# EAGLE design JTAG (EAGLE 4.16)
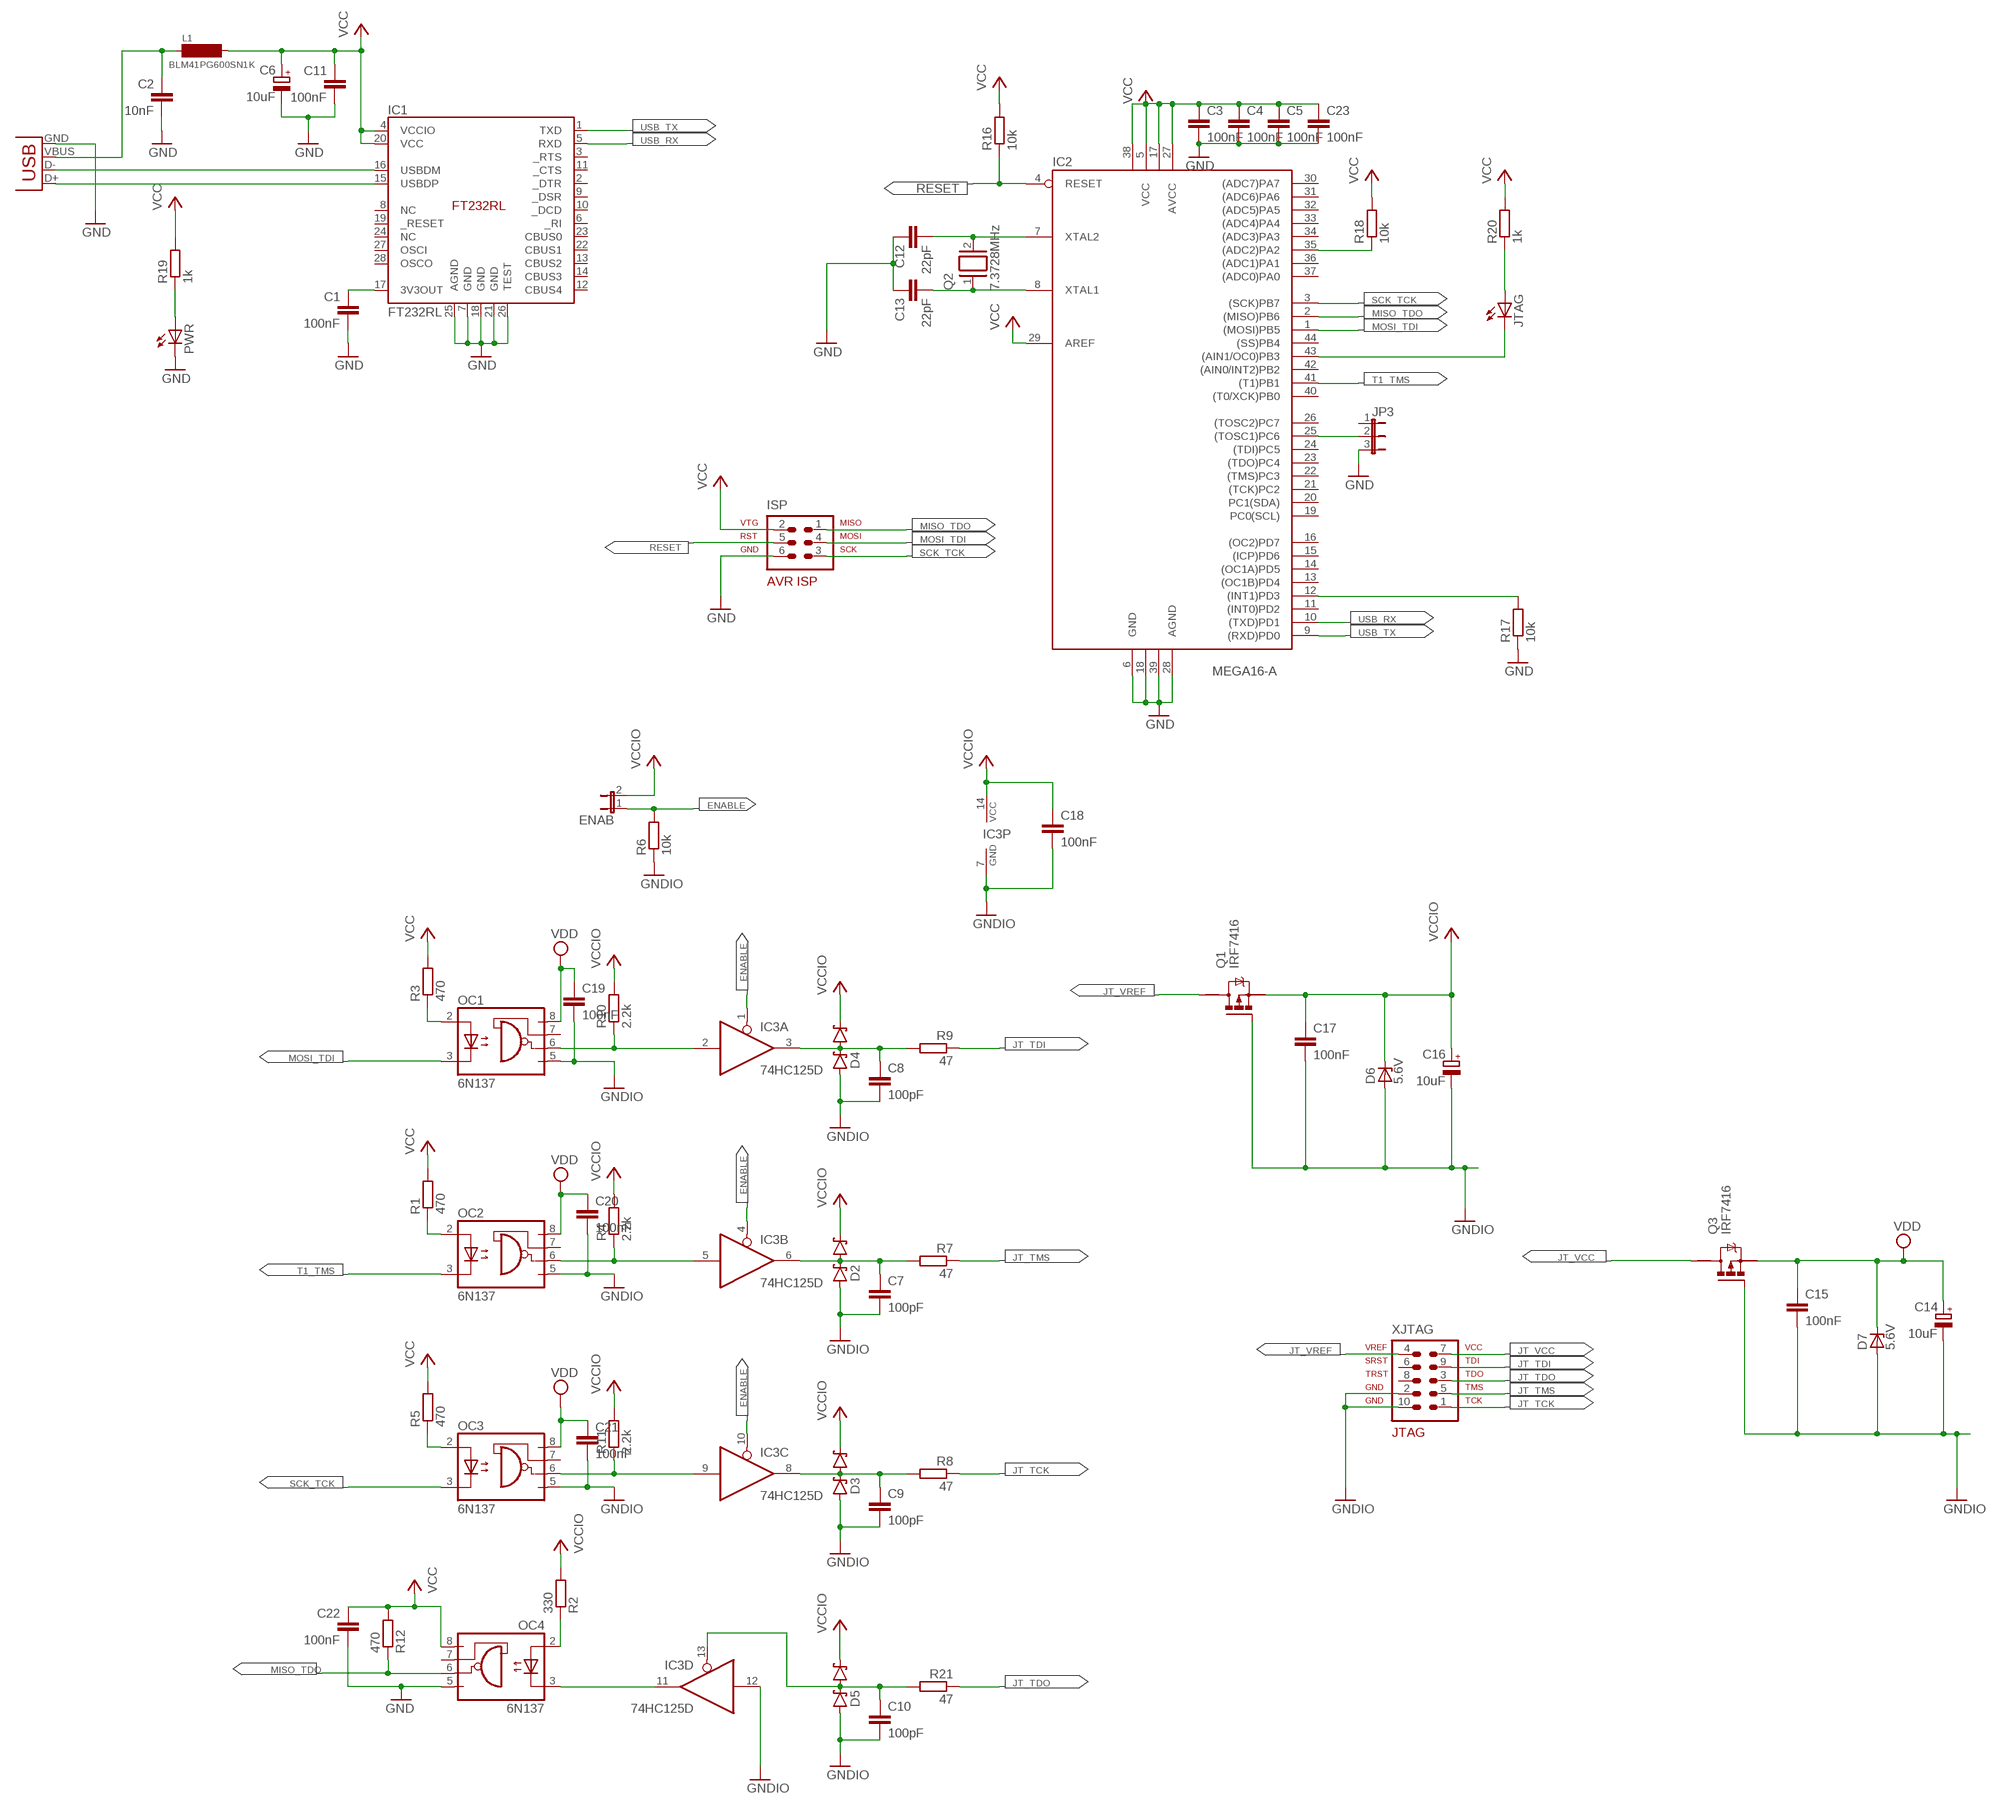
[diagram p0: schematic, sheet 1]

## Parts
C1  100nF  C-EUC0805  [C0805]
C2  10nF  C-EUC0805  [C0805]
C3  100nF  C-EUC0805  [C0805]
C4  100nF  C-EUC0805  [C0805]
C5  100nF  C-EUC0805  [C0805]
C6  10uF  CPOL-EUB  [PANASONIC_B]
C7  100pF  C-EUC0805  [C0805]
C8  100pF  C-EUC0805  [C0805]
C9  100pF  C-EUC0805  [C0805]
C10  100pF  C-EUC0805  [C0805]
C11  100nF  C-EUC0805  [C0805]
C12  22pF  C-EUC0805  [C0805]
C13  22pF  C-EUC0805  [C0805]
C14  10uF  CPOL-EUB  [PANASONIC_B]
C15  100nF  C-EUC0805  [C0805]
C16  10uF  CPOL-EUB  [PANASONIC_B]
C17  100nF  C-EUC0805  [C0805]
C18  100nF  C-EUC0805  [C0805]
C19  100nF  C-EUC0805  [C0805]
C20  100nF  C-EUC0805  [C0805]
C21  100nF  C-EUC0805  [C0805]
C22  100nF  C-EUC0805  [C0805]
C23  100nF  C-EUC0805  [C0805]
D2  DUAL_SCHOTTKY_CACASOT23  [SOT23]
D3  DUAL_SCHOTTKY_CACASOT23  [SOT23]
D4  DUAL_SCHOTTKY_CACASOT23  [SOT23]
D5  DUAL_SCHOTTKY_CACASOT23  [SOT23]
D6  5.6V  ZENER-DIODESOT23  [SOT23]
D7  5.6V  ZENER-DIODESOT23  [SOT23]
ENAB  JP1E  [JP1]
IC1  FT232RL  [SSOP-28]
IC2  MEGA16-A  [TQFP44]
IC3  74HC125D  [SO14]
ISP  AVR-ISP-6  [AVR-ISP-6]
JP3  JP2E  [JP2]
JTAG  LED5MM  [LED5MM]
L1  BLM41PG600SN1K  [1806]
OC1  6N137  [DIL08]
OC2  6N137  [DIL08]
OC3  6N137  [DIL08]
OC4  6N137  [DIL08]
PWR  LED5MM  [LED5MM]
Q1  IRF7416  P-MOSFET-SO8  [SO-08]
Q2  7.3728MHz  XTAL/S  [QS]
Q3  IRF7416  P-MOSFET-SO8  [SO-08]
R1  470  R-EU_R0805  [R0805]
R2  330  R-EU_R0805  [R0805]
R3  470  R-EU_R0805  [R0805]
R4  2.2k  R-EU_R0805  [R0805]
R5  470  R-EU_R0805  [R0805]
R6  10k  R-EU_R0805  [R0805]
R7  47  R-EU_R0805  [R0805]
R8  47  R-EU_R0805  [R0805]
R9  47  R-EU_R0805  [R0805]
R10  2.2k  R-EU_R0805  [R0805]
R11  2.2k  R-EU_R0805  [R0805]
R12  470  R-EU_R0805  [R0805]
R16  10k  R-EU_R0805  [R0805]
R17  10k  R-EU_R0805  [R0805]
R18  10k  R-EU_R0805  [R0805]
R19  1k  R-EU_R0805  [R0805]
R20  1k  R-EU_R0805  [R0805]
R21  47  R-EU_R0805  [R0805]
USB  USB-B-H  [USB-B-H]
XJTAG  AVR-JTAG-10-R  [AVR-JTAG-10R]

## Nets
D+: IC1.15(USBDP) USB.D+
D-: IC1.16(USBDM) USB.D-
ENABLE: ENAB.1 IC3.1(A:OE) IC3.4(B:OE) IC3.10(C:OE) R6.2
GND: C1.2 C2.2 C3.2 C4.2 C5.2 C6.- C11.2 C12.1 C13.1 C22.2 C23.2 IC1.7(GND) IC1.18(GND) IC1.21(GND) IC1.25(AGND) IC1.26(TEST) IC2.6(GND) IC2.18(GND1) IC2.28(AGND) IC2.39(GND2) ISP.6 JP3.3 OC4.5(GND) PWR.K(C) R17.1 USB.GND
GNDIO: C7.2 C8.2 C9.2 C10.2 C14.- C15.2 C16.- C17.2 C18.2 C19.2 C20.2 C21.2 D2.1(A) D3.1(A) D4.1(A) D5.1(A) D6.1(A) D7.1(A) IC3.7(P:GND) IC3.12(D:I) OC1.5(GND) OC2.5(GND) OC3.5(GND) Q1.4(G) Q3.4(G) R6.1 XJTAG.2 XJTAG.10
JT_TCK: R8.1 XJTAG.1
JT_TDI: R9.1 XJTAG.9
JT_TDO: R21.1 XJTAG.3
JT_TMS: R7.1 XJTAG.5
JT_VCC: Q3.5(D) XJTAG.7
JT_VREF: Q1.5(D) XJTAG.4
MISO_TDO: IC2.2((MISO)PB6) ISP.1 OC4.6(VO) R12.1
MOSI_TDI: IC2.1((MOSI)PB5) ISP.4 OC1.3(C)
N$1: IC2.12((INT1)PD3) R17.2
N$4: C13.2 IC2.8(XTAL1) Q2.1
N$5: C12.2 IC2.7(XTAL2) Q2.2
N$6: IC2.25((TOSC1)PC6) JP3.2
N$8: C8.1 D4.3(AC) IC3.3(A:O) R9.2
N$9: IC2.35((ADC2)PA2) R18.1
N$10: PWR.A R19.1
N$11: OC4.2(A) R2.1
N$12: C7.1 D2.3(AC) IC3.6(B:O) R7.2
N$13: JTAG.A R20.1
N$14: OC1.2(A) R3.1
N$15: OC2.2(A) R1.1
N$17: IC3.5(B:I) OC2.6(VO) R4.1
N$18: C9.1 D3.3(AC) IC3.8(C:O) R8.2
N$20: C10.1 D5.3(AC) IC3.13(D:OE) R21.2
N$21: IC3.11(D:O) OC4.3(C)
N$22: IC2.43((AIN1/OC0)PB3) JTAG.K(C)
N$24: IC3.2(A:I) OC1.6(VO) R10.1
N$26: C2.1 L1.P$1 USB.VBUS
N$35: C1.1 IC1.17(3V3OUT)
N$36: OC3.2(A) R5.1
N$37: IC3.9(C:I) OC3.6(VO) R11.1
RESET: IC2.4(RESET) ISP.5 R16.1
SCK_TCK: IC2.3((SCK)PB7) ISP.3 OC3.3(C)
T1_TMS: IC2.41((T1)PB1) OC2.3(C)
USB_RX: IC1.5(RXD) IC2.10((TXD)PD1)
USB_TX: IC1.1(TXD) IC2.9((RXD)PD0)
VCC: C3.1 C4.1 C5.1 C6.+ C11.1 C22.1 C23.1 IC1.4(VCCIO) IC1.20(VCC) IC2.5(VCC) IC2.17(VCC1) IC2.27(AVCC) IC2.29(AREF) IC2.38(VCC2) ISP.2 L1.P$2 OC4.8(VCC) R1.2 R3.2 R5.2 R12.2 R16.2 R18.2 R19.2 R20.2
VCCIO: C16.+ C17.1 C18.1 D2.2(C) D3.2(C) D4.2(C) D5.2(C) D6.3(C) ENAB.2 IC3.14(P:VCC) Q1.1(S) R2.2 R4.2 R10.2 R11.2
VDD: C14.+ C15.1 C19.1 C20.1 C21.1 D7.3(C) OC1.8(VCC) OC2.8(VCC) OC3.8(VCC) Q3.1(S)
Unconnected: IC1.2(_DTR) IC1.3(_RTS) IC1.6(_RI) IC1.8(NC) IC1.9(_DSR) IC1.10(_DCD) IC1.11(_CTS) IC1.12(CBUS4) IC1.13(CBUS2) IC1.14(CBUS3) IC1.19(_RESET) IC1.22(CBUS1) IC1.23(CBUS0) IC1.24(NC) IC1.27(OSCI) IC1.28(OSCO) IC2.11((INT0)PD2) IC2.13((OC1B)PD4) IC2.14((OC1A)PD5) IC2.15((ICP)PD6) IC2.16((OC2)PD7) IC2.19(PC0(SCL)) IC2.20(PC1(SDA)) IC2.21((TCK)PC2) IC2.22((TMS)PC3) IC2.23((TDO)PC4) IC2.24((TDI)PC5) IC2.26((TOSC2)PC7) IC2.30((ADC7)PA7) IC2.31((ADC6)PA6) IC2.32((ADC5)PA5) IC2.33((ADC4)PA4) IC2.34((ADC3)PA3) IC2.36((ADC1)PA1) IC2.37((ADC0)PA0) IC2.40((T0/XCK)PB0) IC2.42((AIN0/INT2)PB2) IC2.44((SS)PB4) JP3.1 OC1.7(VE) OC2.7(VE) OC3.7(VE) OC4.7(VE) Q1.2(S) Q1.3(S) Q1.6(D) Q1.7(D) Q1.8(D) Q3.2(S) Q3.3(S) Q3.6(D) Q3.7(D) Q3.8(D) XJTAG.6 XJTAG.8

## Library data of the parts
C1-C5 C7-C13 C15 C17-C23 = thomas4:C-EU: CAPACITOR, European symbol
C6 C14 C16 = thomas4:CPOL-EU: POLARIZED CAPACITOR, European symbol
D2-D5 = Thomas2:DUAL_SCHOTTKY_CACA: 2 Diodes - Cathode-Anode|Cathode-Anode
D6 D7 = diode:ZENER-DIODE: Z-Diode
ENAB = thomas-jumper:JP1E: JUMPER
IC1 = thomas-ftdi:FT232RL
IC2 = atmel2:MEGA16: MICROCONTROLLER 16 Kbytes FLASH 1 kbytes SRAM 512 bytes EEPROM USART 8-channel 10 bit ADC
IC3 = thomas-74:74*125: Quad bus BUFFER, 3-state
ISP = atmel2:AVR-ISP-6: AVR ISP-6 Serial Programming Header
JP3 = thomas-jumper:JP2E: JUMPER
JTAG PWR = led:LED: LED
L1 = Thomas:BLM41
OC1-OC4 = thomas5:6N137: MOTOROLA OPTO COUPLER
Q1 Q3 = transistor-power:P-MOSFET-SO8: P-Channel MOSFET Example: FDS4435A; P-Channel Logic Level PowerTrench® MOSFET FDS4465; P-Channel 1.8V Specified PowerTrench® MOSFET Source: www.fairchildsemi.com
Q2 = special:XTAL/S: CRYSTAL
R1-R12 R16-R21 = thomas4:R-EU_
USB = thomas-usb:USB: USB Connectors
XJTAG = atmel2:AVR-JTAG-10: AVR JTAG Debug/Programming Header

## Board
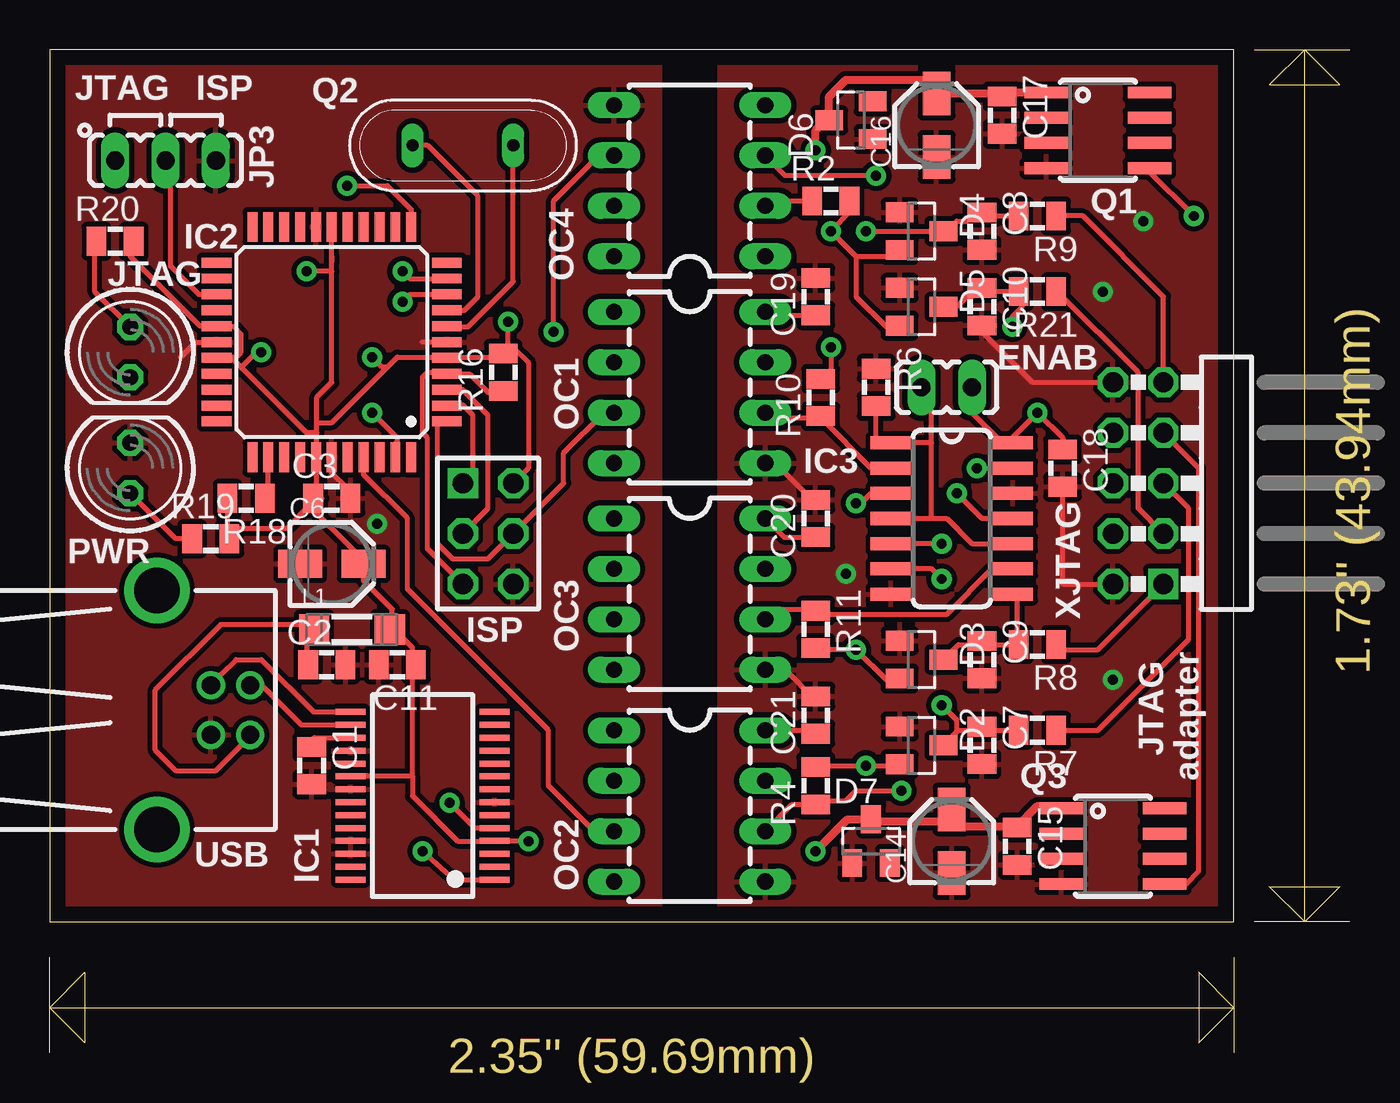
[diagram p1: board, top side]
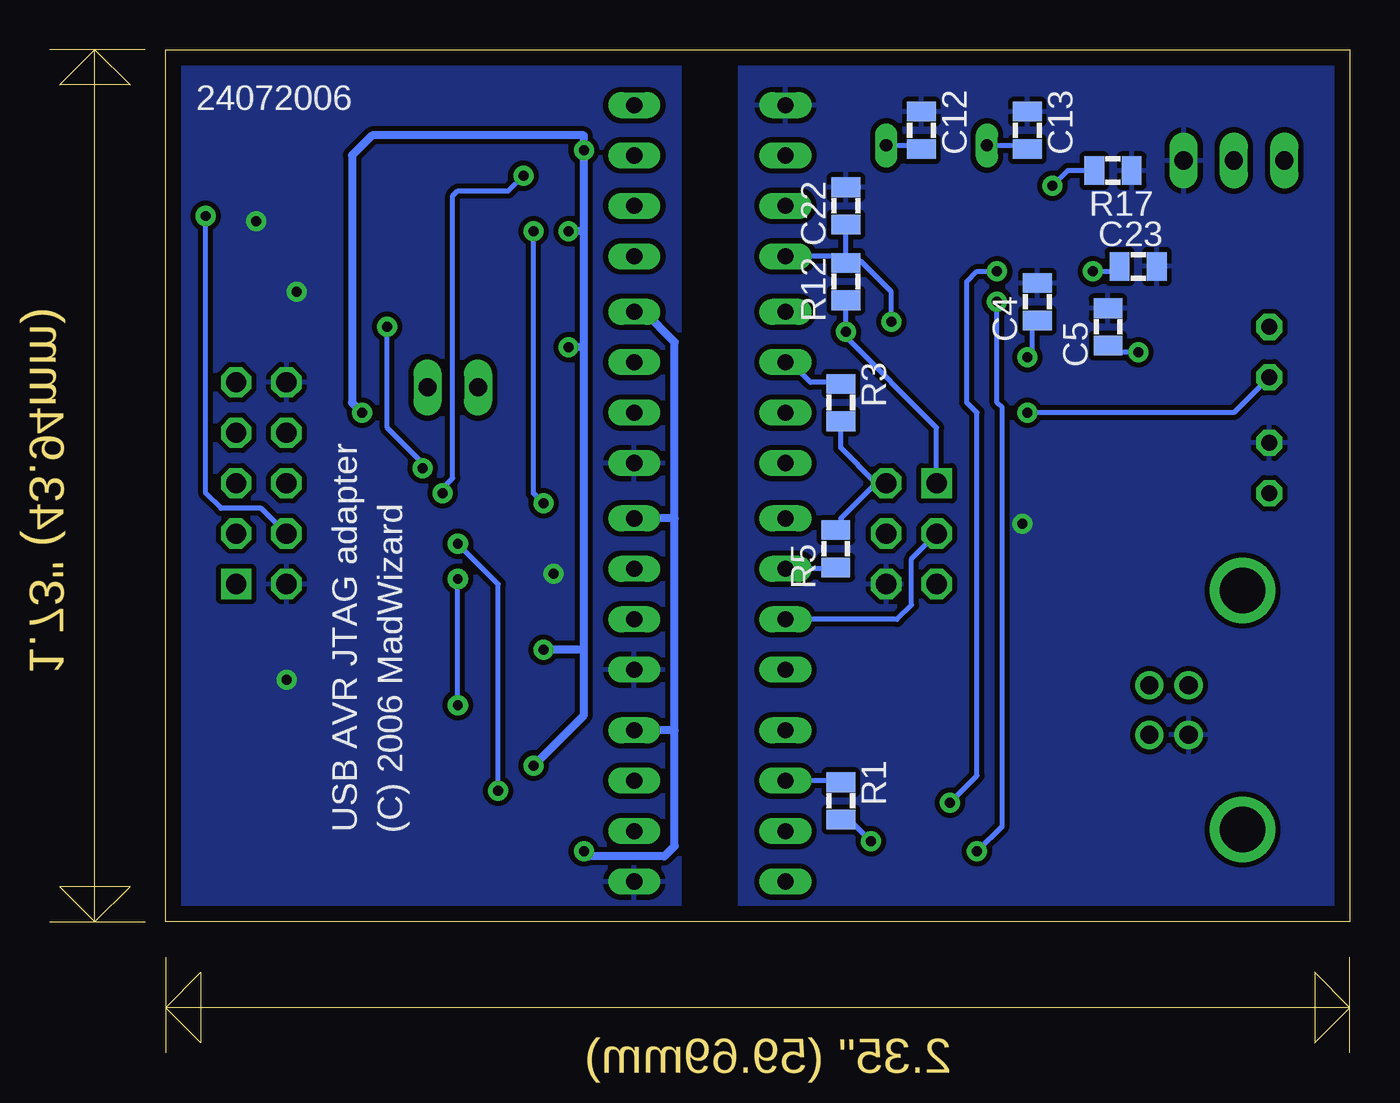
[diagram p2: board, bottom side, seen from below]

Size 65.53 x 50.55 mm. Coordinates in mm from the lower left corner, seen from the top.
Outline: 59.69,4.83 59.69,2.29
Outline: 59.69,2.29 59.69,0
Outline: 0,0 0,2.29
Outline: 0,2.29 0,4.83
Outline: 0,2.29 59.69,2.29
Outline: 59.69,2.29 57.91,4.06 57.91,0.51 59.69,2.29
Outline: 0,2.29 1.78,4.06 1.78,0.51 0,2.29
Outline: 60.71,50.55 63.25,50.55
Outline: 63.25,50.55 65.53,50.55
Outline: 65.53,6.6 63.25,6.6
Outline: 63.25,6.6 60.71,6.6
Outline: 63.25,6.6 63.25,50.55
Outline: 63.25,50.55 61.47,48.77 65.02,48.77 63.25,50.55
Outline: 63.25,6.6 61.47,8.38 65.02,8.38 63.25,6.6
Outline: 0,6.6 59.69,6.6 59.69,50.55 0,50.55 0,6.6
Copper layers (1*16): Top 0.0175mm / dielectric 1.55mm / Bottom 0.0175mm
Design rules "default": minimum track width 10mil, minimum drill 16mil, track to track 9mil, track to pad 9mil, pad to pad 9mil, via to via 9mil, smd to smd 9mil, copper to edge 30mil, drill to drill 10mil, minimum pad ring 10mil, minimum via ring 10mil, stop-mask expansion 4mil, vias tented up to drill 0mil, thermal gap 10mil

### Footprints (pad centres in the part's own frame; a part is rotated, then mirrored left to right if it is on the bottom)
C0805 = smd 0.991 x 1.448: 1 -0.94,0; 2 0.94,0
PANASONIC_B = smd 2.2 x 1.4: + 1.6,0; - -1.6,0
SOT23 = smd 1 x 1.4: 1 -0.95,-1.1; 2 0.95,-1.1; 3 0,1.1
JP1 = drill 0.914 long: 1 0,-1.27; 2 0,1.27
SSOP-28 = smd 0.3 x 1.5: 1 -4.225,-3.625; 2 -3.575,-3.625; 3 -2.925,-3.625; 4 -2.275,-3.625; 5 -1.625,-3.625; 6 -0.975,-3.625; 7 -0.325,-3.625; 8 0.325,-3.625; 9 0.975,-3.625; 10 1.625,-3.625; 11 2.275,-3.625; 12 2.925,-3.625; 13 3.575,-3.625; 14 4.225,-3.625; 15 4.225,3.625; 16 3.575,3.625; 17 2.925,3.625; 18 2.275,3.625; 19 1.625,3.625; 20 0.975,3.625; 21 0.325,3.625; 22 -0.325,3.625; 23 -0.975,3.625; 24 -1.625,3.625; 25 -2.275,3.625; 26 -2.925,3.625; 27 -3.575,3.625; 28 -4.225,3.625
TQFP44 = smd 1.5 x 0.5: 1 -5.8,4; 2 -5.8,3.2; 3 -5.8,2.4; 4 -5.8,1.6; 5 -5.8,0.8; 6 -5.8,0; 7 -5.8,-0.8; 8 -5.8,-1.6; 9 -5.8,-2.4; 10 -5.8,-3.2; 11 -5.8,-4; 23 5.8,-4; 24 5.8,-3.2; 25 5.8,-2.4; 26 5.8,-1.6; 27 5.8,-0.8; 28 5.8,0; 29 5.8,0.8; 30 5.8,1.6; 31 5.8,2.4; 32 5.8,3.2; 33 5.8,4 | smd 0.5 x 1.5: 12 -4,-5.8; 13 -3.2,-5.8; 14 -2.4,-5.8; 15 -1.6,-5.8; 16 -0.8,-5.8; 17 0,-5.8; 18 0.8,-5.8; 19 1.6,-5.8; 20 2.4,-5.8; 21 3.2,-5.8; 22 4,-5.8; 34 4,5.8; 35 3.2,5.8; 36 2.4,5.8; 37 1.6,5.8; 38 0.8,5.8; 39 0,5.8; 40 -0.8,5.8; 41 -1.6,5.8; 42 -2.4,5.8; 43 -3.2,5.8; 44 -4,5.8
SO14 = smd 0.66 x 2.032: 1 -3.81,-3.073; 2 -2.54,-3.073; 3 -1.27,-3.073; 4 0,-3.073; 5 1.27,-3.073; 6 2.54,-3.073; 7 3.81,-3.073; 8 3.81,3.073; 9 2.54,3.073; 10 1.27,3.073; 11 0,3.073; 12 -1.27,3.073; 13 -2.54,3.073; 14 -3.81,3.073
AVR-ISP-6 = drill 1.016 square: 1 -2.54,-1.27 | drill 1.016 octagon: 2 -2.54,1.27; 3 0,-1.27; 4 0,1.27; 5 2.54,-1.27; 6 2.54,1.27
JP2 = drill 0.914 long: 1 -2.54,0; 2 0,0; 3 2.54,0
LED5MM = drill 0.813 octagon: A -1.27,0; K 1.27,0
1806 = smd 1.524 x 1.524: P$1 -1.905,0; P$2 1.905,0
DIL08 = drill 0.813 long: 1 -3.81,-3.81; 2 -1.27,-3.81; 3 1.27,-3.81; 4 3.81,-3.81; 5 3.81,3.81; 6 1.27,3.81; 7 -1.27,3.81; 8 -3.81,3.81
SO-08 = smd 0.6 x 2.2: 1 -1.905,-2.6; 2 -0.635,-2.6; 3 0.635,-2.6; 4 1.905,-2.6; 5 1.905,2.6; 6 0.635,2.6; 7 -0.635,2.6; 8 -1.905,2.6
QS = drill 0.61 long: 1 -2.54,0; 2 2.54,0
R0805 = smd 0.991 x 1.448: 1 -0.94,0; 2 0.94,0
USB-B-H = drill 0.914 round: D+ 0,1.25; D- 1.981,1.25; GND 0,-1.25; VBUS 1.981,-1.25 | drill 2.286 round: P$1 -2.718,-6.02; P$2 -2.718,6.02
AVR-JTAG-10R = drill 1.016 square: 1 -5.08,-1.27 | drill 1.016 octagon: 2 -5.08,1.27; 3 -2.54,-1.27; 4 -2.54,1.27; 5 0,-1.27; 6 0,1.27; 7 2.54,-1.27; 8 2.54,1.27; 10 5.08,1.27 | drill 1.016 pad 1.422 octagon: 9 5.08,-1.27

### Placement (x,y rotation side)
C1  13.21,14.48 270 top
C2  13.97,19.56 0 top
C3  14.22,27.94 0 top
C4  15.75,37.85 90 bottom
C5  12.19,36.58 90 bottom
C6  14.22,24.64 0 top
C7  46.99,15.49 270 top
C8  46.99,41.4 270 top
C9  46.99,19.81 270 top
C10  46.99,37.59 270 top
C11  17.53,19.56 180 top
C12  21.59,46.48 270 bottom
C13  16.26,46.48 270 bottom
C14  45.47,10.67 90 top
C15  48.77,10.41 270 top
C16  44.7,46.74 90 top
C17  48.01,47.24 270 top
C18  51.05,29.46 270 top
C19  38.61,38.1 90 top
C20  38.61,26.92 90 top
C21  38.61,17.02 90 top
C22  25.4,42.67 90 bottom
C23  10.67,39.62 0 bottom
D2  43.94,15.49 270 top
D3  43.94,19.81 270 top
D4  43.94,41.4 270 top
D5  43.94,37.59 270 top
D6  40.39,46.99 90 top
D7  41.4,10.67 0 top
ENAB  45.21,33.53 270 top
IC1  18.8,12.95 90 top
IC2  14.22,35.81 180 top
IC3  45.47,26.92 270 top
ISP  22.1,26.16 270 top
JP3  5.84,44.96 0 top
JTAG  4.06,35.31 270 top
L1  15.24,21.34 0 top
OC1  32.26,33.53 270 top
OC2  32.26,12.45 270 top
OC3  32.26,23.11 270 top
OC4  32.26,43.94 90 top
PWR  4.06,29.46 90 top
Q1  52.83,46.48 270 top
Q2  20.83,45.72 0 top
Q3  53.59,10.41 270 top
R1  25.65,12.7 270 bottom
R2  39.37,42.93 0 top
R3  25.65,32.77 270 bottom
R4  38.61,13.46 90 top
R5  25.91,25.4 90 bottom
R6  41.66,33.53 270 top
R7  49.78,16.26 180 top
R8  49.78,20.57 180 top
R9  49.78,42.16 180 top
R10  38.86,33.02 90 top
R11  38.61,21.34 270 top
R12  25.4,38.86 90 bottom
R16  22.86,34.29 90 top
R17  11.94,44.45 180 bottom
R18  9.91,27.94 180 top
R19  8.13,25.91 0 top
R20  3.3,40.89 0 top
R21  49.78,38.35 180 top
USB  8.13,17.27 0 top
XJTAG  54.86,28.7 90 top

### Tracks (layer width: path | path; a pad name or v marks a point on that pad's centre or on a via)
D+
  Top 0.254: IC1.15 13.3,17.18 10.67,19.81 9.4,19.81 8.66,19.07 8.15,18.52 8.13,18.54 USB.D+
D-
  Top 0.254: USB.D- 10.14,18.52 10.41,18.8 12.68,16.53 IC1.16
ENABLE
  Top 0.254: IC3.10 46.48,25.65 45.21,26.92 44.45,26.92 | IC3.4 44.45,26.92 | 44.45,26.92 44.45,30.73 | 44.45,30.73 44.45,33.53 ENAB.1 | 44.45,30.73 IC3.1 | IC3.1 42.42,30.73 | IC3.1 41.66,30.73 R6.2
GND  (via drill 0.5)
  Top 0.254: IC2.28 7.37,35.81 6.6,35.05 | IC2.6 18.8,35.81 | IC2.39 14.22,29.21 14.99,28.45 14.99,27.94 C3.2
  other vias: 16.51,26.67
  pour Bottom (isolate 0.254): -8.38,50.8 30.73,52.32 30.73,2.54 -7.87,3.56
  pour Top (isolate 0.254): -6.1,51.56 30.73,52.32 30.73,3.3 -6.1,4.32
GNDIO  (via drill 0.5)
  Top 0.254: C21.2 38.61,17.78 37.08,19.3 OC3.5 | C9.2 46.99,18.8 46.92,18.86 | C7.2 46.99,14.48 46.92,14.54 | 47.24,36.58 C10.2 46.99,36.32 49.53,33.78 XJTAG.10 | OC1.5 36.58,29.72 38.35,27.94 38.53,27.94 C20.2 | XJTAG.2 51.05,23.62 C18.2 51.05,28.7
  other vias: 40.13,24.13 53.59,18.8 53.09,38.35 55.12,41.91
  pour Bottom (isolate 0.254): 61.72,3.56 33.78,3.56 33.78,53.59 62.48,54.1
  pour Top (isolate 0.254): 63.25,2.03 33.78,1.27 33.78,56.9 62.99,53.09 64.26,11.68
JT_TCK
  Top 0.254: R8.1 50.8,20.32 52.83,20.32 XJTAG.1
JT_TDI
  Top 0.254: 50.55,42.16 R9.1 52.07,42.16 56.13,38.1 XJTAG.9
JT_TDO
  Top 0.254: XJTAG.3 54.86,27.43 54.86,34.29 50.8,38.35 R21.1
JT_TMS
  Top 0.254: R7.1 52.83,16.26 57.4,20.84 57.4,27.43 XJTAG.5
JT_VCC
  Top 0.254: XJTAG.7 57.91,29.46 57.91,9.14 57.28,8.51 Q3.5
JT_VREF  (via drill 0.5)
  Top 0.254: v57.66,42.16 55.37,44.45 55.43,44.51 Q1.5
  Bottom 0.254: v57.66,42.16 57.66,28.19 56.9,27.43 54.86,27.43 XJTAG.4
MISO_TDO  (via drill 0.5)
  Top 0.254: IC2.2 19.96,32.61 20.07,32.51 20.83,32.64 21.34,32.13 21.34,29.46 ISP.1 | OC4.6 27.69,45.21 25.4,42.93 v25.4,36.32
  Bottom 0.254: R12.1 v25.4,36.32 25.4,36.07 20.83,31.5 ISP.1
MOSI_TDI
  Top 0.254: IC2.1 19.62,31.81 19.56,31.75 19.56,25.65 20.32,24.89 22.1,24.89 ISP.4 25.91,28.7 25.91,30.23 27.94,32.26 OC1.3
N$1  (via drill 0.5)
  Top 0.254: IC2.12 18.22,42.48 17.02,43.69 v14.99,43.69
  Bottom 0.254: R17.2 14.22,44.45 v14.99,43.69
N$4
  Top 0.254: IC2.8 20.9,37.41 21.59,38.1 21.59,43.18 19.05,45.72 Q2.1
  Bottom 0.254: C13.2 16.26,45.72 Q2.1 18.2,45.63
N$5
  Top 0.254: Q2.2 23.37,38.86 21.08,36.58 20.07,36.58 IC2.7
  Bottom 0.254: C12.2 21.59,45.72 Q2.2 23.28,45.63
N$6
  Top 0.254: IC2.25 7.51,38.21 6.1,39.62 6.1,44.2 5.84,44.45 JP3.2
N$8  (via drill 0.5)
  Top 0.254: 45.21,41.4 45.21,41.66 | 49.02,42.16 R9.2 47.24,42.16 47.07,42.34 C8.1 46.66,42.34 46.23,41.91 45.72,41.91 45.21,41.4 | v40.64,27.69 40.89,27.69 41.4,28.19 IC3.3 | v41.15,41.4 D4.3 45.21,41.4
  Bottom 0.254: v40.64,27.69 41.15,28.19 v41.15,41.4
N$9
  Top 0.254: R18.1 10.92,27.94 11.02,28.04 IC2.35
N$10
  Top 0.254: R19.1 6.35,25.91 PWR.A
N$11
  Top 0.254: R2.1 36.32,42.93 OC4.2
N$12  (via drill 0.5)
  Top 0.254: 47.08,16.26 47.24,16.26 | D2.3 45.76,16.21 | 45.76,16.21 45.8,16.26 47.08,16.26 | 49.02,16.26 R7.2 47.08,16.26 | 47.08,16.26 C7.1 | v44.96,23.88 44.45,24.38 IC3.6 | 45.76,16.21 45.72,16.26 45.72,16.76 v44.96,17.53
  Bottom 0.254: v44.96,17.53 v44.96,23.88
N$13
  Top 0.254: R20.1 2.29,40.89 2.29,38.35 JTAG.A
N$14
  Bottom 0.254: OC1.2 28.19,34.8 27.18,33.78 25.65,33.78 R3.1
N$15
  Bottom 0.254: R1.1 26.42,13.72 OC2.2
N$17  (via drill 0.5)
  Top 0.254: v42.93,13.21 40.64,13.21 40.13,12.7 38.86,12.7 38.77,12.61 R4.1 37.41,12.52 OC2.6 | v44.96,25.65 IC3.5
  Bottom 0.254: v42.93,13.21 42.93,23.62 v44.96,25.65
N$18
  Top 0.254: D3.3 45.8,20.57 46.99,20.57 C9.1 47.08,20.57 R8.2 48.77,20.74 48.77,23.11 IC3.8
N$20  (via drill 0.5)
  Top 0.254: D5.3 45.72,37.59 46.23,38.1 46.48,38.1 46.99,38.61 C10.1 46.99,38.35 R21.2 49.02,38.35 49.02,37.59 48.51,37.08 v48.51,36.58 | v46.74,29.46 IC3.13
  Bottom 0.254: v46.74,29.46 46.74,29.72 48.51,31.5 v48.51,36.58
N$21  (via drill 0.5)
  Top 0.254: OC4.3 37.08,44.2 v41.66,44.2 | IC3.11 46.99,26.92 v45.72,28.19
  Bottom 0.254: v45.72,28.19 45.72,28.45 45.21,28.96 45.21,43.18 44.96,43.43 42.42,43.43 v41.66,44.2
N$22  (via drill 0.5)
  Top 0.254: 17.48,30.01 17.53,29.97 | 17.48,30.01 IC2.43 | 17.48,30.01 17.48,30.78 17.53,30.78 17.53,30.99 v16.26,32.26
  Bottom 0.254: v16.26,32.26 5.84,32.26 JTAG.K
N$24
  Top 0.254: 42.42,29.46 IC3.2 41.4,29.46 38.86,32 R10.1 38.79,32 35.81,32 OC1.6
N$26
  Top 0.254: 13.21,21.59 8.64,21.59 5.33,18.29 5.33,15.24 6.35,14.22 8.38,14.22 10.16,16 10.14,16.02 USB.VBUS | 13.21,21.59 L1.P$1 | C2.1 12.95,19.56 12.95,21.08 12.87,21.17 13.21,21.59
N$35
  Top 0.254: C1.1 13.21,15.75 13.34,15.88 IC1.17
N$36
  Bottom 0.254: R5.1 25.91,24.38 OC3.2
N$37
  Top 0.254: IC3.9 47.5,24.38 45.21,22.1 39.2,22.1 R11.1 38.53,22.28 38.35,22.35 36.83,22.35 36.07,21.59 OC3.6
RESET
  Top 0.254: ISP.5 19.05,25.4 19.05,30.99 18.8,31.24 18.8,34.04 19.05,34.29 20.07,34.29 20.02,34.25 IC2.4 21.16,34.21 22.1,33.27 22.86,33.27 R16.1
SCK_TCK
  Top 0.254: IC2.3 20.82,33.41 22.1,32.13 22.1,27.43 ISP.3
  Bottom 0.254: OC3.3 22.82,21.84 22.1,22.56 22.1,24.89 ISP.3
T1_TMS
  Top 0.254: 28.7,11.18 OC2.3 27.43,11.18 25.15,13.46 25.15,16.26 18.03,23.37 18.03,26.92 15.82,29.13 IC2.41
USB_RX  (via drill 0.5)
  Top 0.254: 20.57,12.19 v20.17,12.6 21.44,11.33 IC1.5 | IC2.10 18.14,39.01 v17.78,39.37
  Bottom 0.254: v17.78,39.37 18.8,39.37 19.3,38.86 19.3,32.77 18.8,32.26 18.8,13.97 v20.17,12.6
USB_TX  (via drill 0.5)
  Top 0.254: 22.45,8.73 IC1.1 20.41,8.73 v18.8,10.16 | IC2.9 18.15,38.21 v17.78,37.85
  Bottom 0.254: v17.78,37.85 17.78,32.77 17.53,32.51 17.53,11.43 v18.8,10.16
VCC  (via drill 0.5)
  Top 0.254: 14.22,41.66 IC2.17 14.22,40.13 | 4.32,40.89 R20.2 4.06,40.89 4.06,40.13 7.58,36.61 IC2.27 8.38,36.58 9.29,36.58 9.65,36.22 9.65,35.31 9.4,35.05 | 13.46,29.97 IC2.38 13.46,29.97 | R16.2 22.86,35.31 23.11,35.56 v23.11,36.83 | R16.2 23.37,35.56 24.13,34.8 24.13,29.46 ISP.2 | IC2.29 8.38,35.05 9.4,35.05 | 18.29,13.97 18.29,19.56 | 18.29,13.97 18.29,12.95 20.57,10.67 22.1,10.67 arc-60 IC1.4 24.37,10.68 v24.13,10.67 | 9.65,34.54 12.95,31.24 13.46,31.24 | 9.65,34.54 9.14,35.05 9.4,35.05 | 17.02,34.54 17.53,35.05 20.07,35.05 | 17.02,34.54 14.22,31.75 13.46,31.75 | 14.22,39.37 14.22,33.78 13.46,33.02 13.46,31.75 | 14.22,39.37 14.22,40.13 | 13.46,31.24 13.46,31.75 | C3.1 13.37,27.27 15.75,24.89 16,24.89 15.75,24.64 C6.+ 15.82,23.8 17.27,22.35 17.27,21.84 17.02,21.59 L1.P$2 17.37,21.34 18.29,20.42 18.29,19.56 | IC1.20 16,13.97 18.29,13.97 | 18.29,19.56 C11.1 | C3.1 13.72,27.94 13.46,28.19 13.46,29.97 | 17.02,34.54 16.76,34.54 v16.26,35.05 | 20.07,35.05 IC2.5 | R16.2 22.86,35.05 20.07,35.05 | C3.1 13.21,27.94 13.21,27.69 11.94,26.42 9.4,26.42 9.14,26.16 arc-180 R19.2 8.89,25.91 8.97,25.98 R18.2 | 14.22,40.13 14.22,39.88 | 14.22,39.37 v12.95,39.37 | 9.65,34.54 10.41,35.31 v10.67,35.31 | 13.46,29.97 13.46,31.24
  Bottom 0.254: R3.2 25.65,30.48 23.88,28.7 | ISP.2 23.88,28.7 | 23.88,28.7 25.65,26.92 25.65,26.42 25.73,26.34 R5.2 | 25.4,39.88 24.64,39.88 23.11,38.35 v23.11,36.83 | OC4.8 25.65,40.13 25.4,39.88 | C5.1 12.19,35.81 11.68,35.31 v10.67,35.31 | v12.95,39.37 11.43,39.37 11.43,39.62 C23.1 | 25.4,39.88 R12.2 | 25.4,39.88 C22.1 | R1.2 25.4,11.68 25.15,11.68 v24.13,10.67 | C4.1 16,37.08 16,35.31 v16.26,35.05
VCCIO  (via drill 0.5)
  Top 0.254: 40.13,42.67 R2.2 40.31,42.42 40.39,42.42 v39.37,41.4 40.64,40.13 | 40.64,40.13 42.42,40.13 42.67,40.39 D4.2 | v39.37,35.56 39.37,34.04 R10.2 | R11.2 38.61,20.57 38.86,20.32 v40.64,20.32 42.16,18.8 42.67,18.8 42.86,18.98 42.93,18.8 D3.2 | R4.2 38.61,14.48 v41.15,14.48 42.93,14.48 D2.2 | ENAB.2 46.48,32.26 48.01,30.73 IC3.14 48.54,30.96 48.51,30.99 v49.78,32.26 51.05,30.99 C18.1 | 48.01,48.01 48.39,48.39 | 48.01,48.01 C17.1 | 47.93,48.34 48.01,48.01 | C16.+ 44.7,48.77 44.45,49.02 | 39.12,46.99 D6.3 | 40.64,40.13 40.64,38.1 42.16,36.58 42.93,36.58 D5.2
  Top 0.406: 48.39,48.39 Q1.1 | C16.+ 47.93,48.34 | D6.3 39.29,48.18 40.13,49.02 44.45,49.02 | 39.12,46.99 38.61,46.48 v38.61,45.47
  Bottom 0.406: v41.15,14.48 38.61,17.02 38.61,20.32 | 38.61,20.32 v40.64,20.32 | 38.61,41.4 v39.37,41.4 | v49.78,32.26 50.29,32.77 50.29,45.21 49.28,46.23 38.61,46.23 38.61,45.72 | 38.61,45.72 v38.61,45.47 | 38.61,35.56 v39.37,35.56 | 38.61,35.56 38.61,41.4 | 38.61,41.4 38.61,45.72 | 38.61,20.32 38.61,35.56
VDD  (via drill 0.5)
  Top 0.254: C21.1 38.61,16.26 OC2.8 36.32,16.26 | 48.77,11.43 C15.1 48.51,11.43 | Q3.1 51.05,12.45 49.78,12.45 | 45.47,11.43 C14.+ 45.21,11.68 | D7.3 41.4,11.68 | C19.1 36.25,37.16 OC1.8 | C20.1 37.01,25.98 OC3.8
  Top 0.406: D7.3 40.22,11.77 v38.61,10.16 | 48.77,11.43 49.78,12.45 | 45.47,11.43 48.51,11.43 | 41.4,11.68 45.21,11.68
  Bottom 0.406: v38.61,10.16 38.35,9.91 34.54,9.91 34.04,10.41 34.04,16.26 | 34.04,16.26 34.04,26.92 | 34.04,26.92 34.04,35.81 35.56,37.34 OC1.8 | 34.04,26.92 OC3.8 | 34.04,16.26 OC2.8

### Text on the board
Top: TOP LAYER COPPER
Bottom: BOTTOM LAYER COPPER
Dimension: MECHANICAL LAYER | 1.73" (43.94mm) | 2.35" (59.69mm)
bPlace: 24072006 | USB AVR JTAG adapter | BOTTOM LAYER SILK SCREEN | (C) 2006 MadWizard
tNames: JTAG | ISP | TOP LAYER SILK SCREEN | JTAG | adapter
tStop: TOP LAYER SOLDER MASK
bStop: BOTTOM LAYER SOLDER MASK
Reference: Layer stack-up: | All layers are in top view | Board is rectangular | Board size is 2.35x1.73 inches | (59.69x43.94mm) | All holes are plated
_tsilk: JTAG | ISP | Q2 | JP3 | TOP LAYER SILK SCREEN | OC4 | Q1 | IC2 | JTAG | ENAB | OC1 | IC3 | PWR | ISP | XJTAG | OC3 | JTAG | Q3 | adapter | OC2 | USB | IC1
_bsilk: 24072006 | USB AVR JTAG adapter | BOTTOM LAYER SILK SCREEN | (C) 2006 MadWizard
